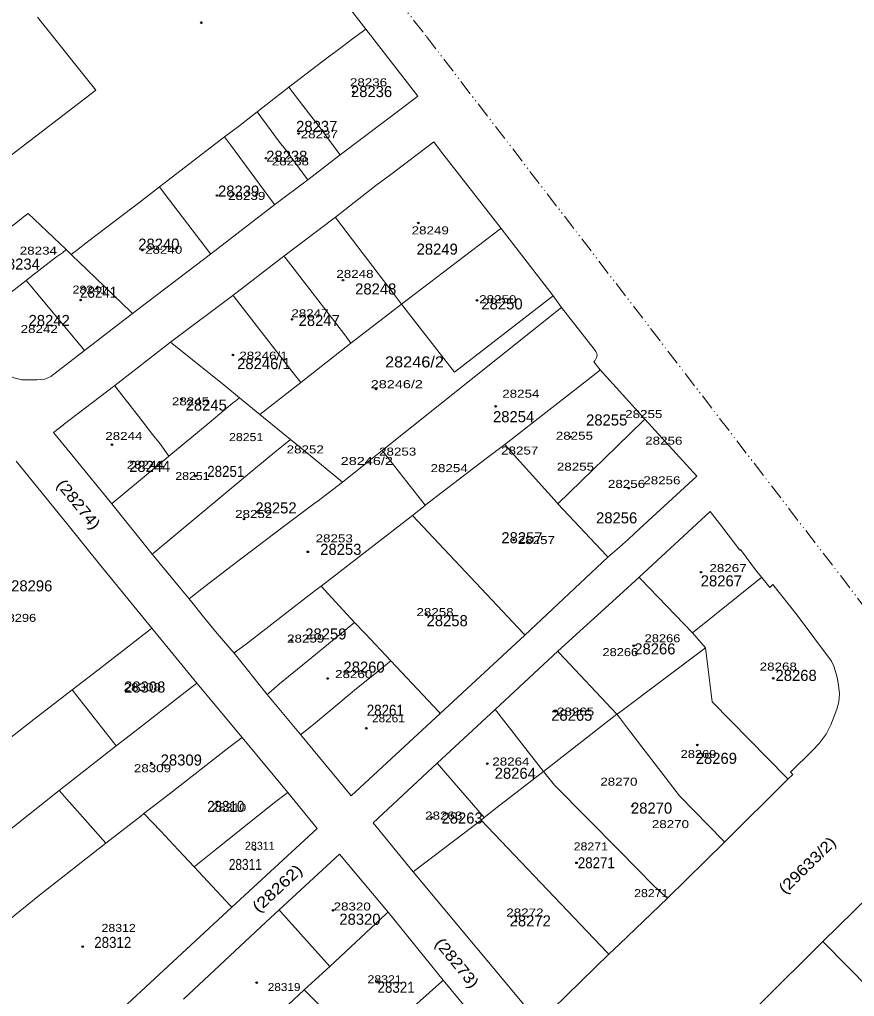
# Model space of a CAD drawing. Extents: x 650553 to 652508, y 239277 to 241647.
# Drawn here: x 651930.1 to 652201.4, y 241075.2 to 241392.6 of the extents above; entities that cross this region are included whole.
import ezdxf

# ---------------------------------------------------------------- set-up
doc = ezdxf.new("R2010")
doc.units = 0
doc.header["$PDMODE"] = 32
doc.header["$PDSIZE"] = 0.5
doc.linetypes.add('DASH_DOUBLE_DOT', pattern=[9.2, 5, -1.2, 0.3, -1.2, 0.3, -1.2])
for name, color, linetype in [('19', 7, 'Continuous'), ('20', 7, 'Continuous'), ('6', 7, 'Continuous')]:
    doc.layers.add(name, color=color, linetype=linetype)
for name, color, linetype, lineweight in [('3', 7, 'Continuous', 13), ('5', 7, 'Continuous', 13), ('52', 7, 'DASH_DOUBLE_DOT', 13)]:
    doc.layers.add(name, color=color, linetype=linetype, lineweight=lineweight)

msp = doc.modelspace()

# ---------------------------------------------------------------- linework, layer by layer
at = {"layer": '3'}
for points in [[(651890.22, 241320.18), (651838.628, 241383.147), (651822.772, 241401.85), (651822.162, 241402.878), (651822.324, 241404.195), (651822.971, 241405.485), (651878.911, 241448.551), (651945.895, 241499.372), (651947.853, 241500.347), (651950.067, 241500.78), (651952.377, 241500.815), (651954.829, 241500.052), (651957.24, 241498.606), (651959.178, 241496.936), (651974.53, 241477.34), (652042.61, 241389.52)], [(652042.61, 241389.52), (652059.5, 241367.66), (652055.39, 241364.52), (652034.26, 241348.65), (652023.73, 241340.54), (652013.04, 241332.49), (651992.17, 241316.41), (651966.8, 241297.11), (651951.21, 241285.1)], [(652032.73, 241328.39), (652045.89, 241338.65), (652050.75, 241342.3), (652064.76, 241352.88)], [(652064.76, 241352.88), (652066.86, 241349.97), (652086.59, 241324.72), (652103.55, 241302.85), (652106.22, 241299.1)], [(651960.07, 241235.27), (651948.05, 241250), (651941.16, 241258.44), (651944.34, 241260.94), (651944.29, 241260.92), (651961.05, 241273.7), (651979.19, 241287.8), (651999.42, 241303), (652016.01, 241315.75), (652032.73, 241328.39)], [(651951.21, 241285.1), (651940.242, 241276.615), (651938.359, 241275.772), (651935.721, 241275.565), (651930.828, 241275.601), (651928.272, 241276.225), (651924.784, 241277.89), (651912.6, 241292.65), (651901.67, 241305.81), (651890.22, 241320.18)], [(652106.22, 241299.1), (652116.84, 241285.49), (652117.34, 241284.77), (652117.73, 241284.14), (652117.75, 241283.42), (652117.6, 241282.82), (652117.38, 241282.34), (652117.06, 241281.74), (652116.74, 241281.45), (652118.8, 241278.81), (652133.285, 241262.755)], [(652133.285, 241262.755), (652150.153, 241244.243), (652131.71, 241227.29), (652127.95, 241223.81), (652125, 241221.2), (652121.3, 241217.93), (652094.34, 241192.6), (652066.77, 241167.17), (652037.87, 241140.4), (652021.41, 241160.31), (652010.56, 241173.28), (651999.81, 241186.77)], [(651929, 241249.08), (651945.44, 241228.9), (651956.13, 241215.68), (651973.06, 241194.89), (651987.72, 241177.05), (652002.397, 241159.358), (652017.226, 241141.527)], [(651985.26, 241204.43), (651982.46, 241207.64), (651973.24, 241218.88), (651960.07, 241235.27)], [(652105.01, 241187.4), (652125, 241205.59), (652131.42, 241211.43), (652154.53, 241232.81)], [(652154.53, 241232.81), (652158.3, 241227.9), (652164.11, 241220.19), (652164.36, 241220.41), (652169.59, 241213.36), (652171.28, 241211.36)], [(652171.28, 241211.36), (652173.87, 241208.14), (652174.89, 241209.06), (652182.74, 241199.12), (652193.93, 241184.19), (652194.75, 241182.55), (652195.76, 241178.96), (652196.2, 241176.3), (652196.52, 241173.55), (652196.32, 241170.97), (652195.66, 241168.53), (652193.75, 241163.5), (652192.17, 241160.44), (652189.93, 241157.46), (652187.72, 241155.1), (652180.61, 241148.14), (652181.34, 241147.34), (652179.79, 241145.85), (652159.18, 241125.35), (652140.6, 241107.17)], [(651999.81, 241186.77), (651994.33, 241193.11), (651990.34, 241197.97), (651985.26, 241204.43)], [(652058.02, 241115.72), (652045.01, 241131.65), (652065.76, 241151.05), (652084.65, 241168.4), (652105.01, 241187.4)], [(652017.226, 241141.527), (652026.85, 241129.84), (651999.05, 241104.25), (651938.56, 241048.11), (651910.25, 241021.92), (651891.181, 241043.471), (651876.36, 241060.41), (651857.991, 241081.221), (651845.55, 241095.34), (651829.37, 241113.9)], [(651983.33, 241074.4), (652010.17, 241099.35), (652014.44, 241103.34), (652034.04, 241121.44)], [(652034.04, 241121.44), (652049.83, 241102.63), (652067.78, 241080.53)], [(652121.57, 241088.99), (652098.88, 241066.75), (652058.02, 241115.72)], [(652140.6, 241107.17), (652125, 241092.27), (652121.57, 241088.99)], [(652150.66, 241053.06), (652170.97, 241073.05), (652191.12, 241093.11), (652206.29, 241107.91)], [(652067.78, 241080.53), (652087.98, 241056.04), (652065.72, 241034.07)]]:
    msp.add_lwpolyline(points, dxfattribs=at)
at = {"layer": '5'}
for p, q in [((651954.88, 241369.62), (651935.96, 241393.37)), ((652035.43, 241384.16), (652038.34, 241386.35)), ((651902.89, 241329.78), (651954.88, 241369.62)), ((651998.65, 241351.86), (651996.74, 241354.45)), ((651932.26, 241307.83), (651934.14, 241305.63)), ((652037.75, 241287.47), (652035.78, 241290.15)), ((652021.49, 241274.69), (652019.39, 241277.35)), ((652018.16, 241256.2), (652013.07, 241252.05)), ((652087.74, 241254.55), (652081.78, 241250)), ((652013.07, 241252.05), (652010.57, 241250)), ((652047.94, 241252.56), (652044.71, 241250)), ((652047.94, 241252.56), (652049.95, 241250)), ((651977.78, 241250), (651963.65, 241238.32)), ((651978.66, 241250.72), (651977.78, 241250)), ((652010.57, 241250), (652006.18, 241246.4)), ((652025.7, 241250), (652035.03, 241242.33)), ((652044.71, 241250), (652035.03, 241242.33)), ((652081.78, 241250), (652061.877, 241234.823)), ((652091.81, 241250), (652104.77, 241235.55)), ((652120.15, 241250), (652105.012, 241235.292)), ((652035.03, 241242.33), (652026.74, 241235.96)), ((652104.77, 241235.55), (652105.012, 241235.292)), ((652061.95, 241234.73), (652057.83, 241231.51)), ((652152.95, 241188.53), (652148.8, 241193.31)), ((652152.95, 241188.53), (652125, 241167.51)), ((651947.2, 241174.85), (651961.55, 241156.66)), ((652124.17, 241166.89), (652125, 241167.51)), ((652127.62, 241162.41), (652125, 241165.81)), ((652065.76, 241151.05), (652081.05, 241133.37)), ((651943.01, 241142.12), (651958.13, 241124.99))]:
    msp.add_line(p, q, dxfattribs=at)
for points in [[(652038.34, 241386.35), (652038.34, 241386.28), (652042.61, 241389.52)], [(652017.58, 241370.58), (652028.69, 241379.04), (652035.43, 241384.16)], [(652007.34, 241362.6), (652017.58, 241370.58), (652021.35, 241365.68), (652025.49, 241360.31), (652026.44, 241359.17)], [(651996.74, 241354.45), (652001.23, 241357.84), (652007.34, 241362.6), (652014.92, 241352.3), (652016.16, 241350.78)], [(652026.44, 241359.17), (652033.888, 241349.15), (652034.26, 241348.65)], [(651975.54, 241338.21), (651978.4, 241340.43), (651993.5, 241351.96), (651996.74, 241354.45)], [(651998.65, 241351.86), (652012.669, 241332.99), (652013.04, 241332.49)], [(652016.16, 241350.78), (652023.36, 241341.04), (652023.73, 241340.54)], [(651946.89, 241316.31), (651948.6, 241317.55), (651952.22, 241320.34), (651969.75, 241333.72), (651975.54, 241338.21), (651977.42, 241335.72)], [(651977.42, 241335.72), (651991.788, 241316.91), (651992.17, 241316.41)], [(651901.67, 241305.81), (651902.17, 241306.192), (651914.22, 241315.39), (651917.79, 241318.11), (651928.9, 241326.49), (651931.27, 241328.35)], [(651931.27, 241328.35), (651932.92, 241329.62), (651945.26, 241317.85)], [(652051.86, 241303.3), (652033.111, 241327.89), (652032.73, 241328.39)], [(652086.59, 241324.72), (652086.09, 241324.341), (652054.18, 241300.13)], [(651912.6, 241292.65), (651913.1, 241293.036), (651932.26, 241307.83), (651933.94, 241309.27), (651942.09, 241315.47), (651944.08, 241316.85), (651945.26, 241317.85)], [(651945.26, 241317.85), (651946.89, 241316.31), (651947.46, 241315.77), (651949.27, 241313.99)], [(652035.78, 241290.15), (652016.396, 241315.25), (652016.01, 241315.75)], [(651949.27, 241313.99), (651966.3, 241297.591), (651966.8, 241297.11)], [(651934.14, 241305.63), (651950.794, 241285.6), (651951.21, 241285.1)], [(652019.39, 241277.35), (651999.809, 241302.5), (651999.42, 241303)], [(652054.18, 241300.13), (652052.27, 241302.78), (652051.86, 241303.3)], [(652054.18, 241300.13), (652071.44, 241278.03), (652103.05, 241302.464), (652103.55, 241302.85)], [(652054.18, 241300.13), (652037.75, 241287.47), (652021.49, 241274.69), (652008.13, 241264.27)], [(652047.94, 241252.56), (652105.72, 241298.701), (652106.22, 241299.1)], [(651997.08, 241273.36), (651979.69, 241287.396), (651979.19, 241287.8)], [(652118.8, 241278.81), (652118.3, 241278.419), (652087.74, 241254.55), (652091.81, 241250)], [(651961.05, 241273.7), (651961.437, 241273.2), (651968.78, 241263.72), (651973.25, 241257.76), (651975.75, 241254.77), (651978.66, 241250.72), (651991.05, 241260.99), (651999.28, 241267.92), (651999.94, 241268.42), (652001.55, 241269.71)], [(652008.13, 241264.27), (652001.55, 241269.71), (651997.08, 241273.36)], [(652008.13, 241264.27), (652018.16, 241256.2), (652025.7, 241250)], [(652133.285, 241262.755), (652132.785, 241262.269), (652120.15, 241250)], [(652049.95, 241250), (652061.877, 241234.823), (652061.95, 241234.73)], [(652006.18, 241246.4), (651973.74, 241219.298), (651973.24, 241218.88)], [(651963.65, 241238.32), (651960.57, 241235.696), (651960.07, 241235.27)], [(652026.74, 241235.96), (652026.14, 241235.58), (652017.04, 241228.77)], [(652105.012, 241235.292), (652120.831, 241218.43), (652121.3, 241217.93)], [(652017.04, 241228.77), (651998.76, 241214.95), (651989.33, 241207.61)], [(652057.83, 241231.51), (652028.13, 241208.49), (652031.56, 241204.71), (652038.97, 241196.72), (652023.91, 241184.36), (652014.59, 241176.76)], [(652057.83, 241231.51), (652093.871, 241193.1), (652094.34, 241192.6)], [(652148.8, 241193.31), (652131.9, 241210.93), (652131.42, 241211.43)], [(652148.8, 241193.31), (652170.78, 241210.959), (652171.28, 241211.36)], [(651989.33, 241207.61), (651985.76, 241204.821), (651985.26, 241204.43)], [(652028.13, 241208.49), (652026.11, 241207.06), (652003.83, 241189.82)], [(651973.06, 241194.89), (651972.56, 241194.495), (651969.58, 241192.14), (651955.5, 241181.26), (651947.2, 241174.85), (651933.89, 241164.53), (651924.37, 241157.06)], [(652038.97, 241196.72), (652042.45, 241193.17), (652050.77, 241184.27)], [(652003.83, 241189.82), (652000.31, 241187.149), (651999.81, 241186.77)], [(652179.79, 241145.85), (652179.3, 241146.35), (652155.14, 241170.98), (652152.95, 241188.53)], [(652105.01, 241187.4), (652105.477, 241186.9), (652124.17, 241166.89)], [(652050.77, 241184.27), (652044.95, 241179.5), (652039.58, 241175.25), (652037.54, 241173.52), (652025.62, 241163.62)], [(652050.77, 241184.27), (652066.302, 241167.67), (652066.77, 241167.17)], [(651987.72, 241177.05), (651983.87, 241174.06), (651967.51, 241161.35), (651961.55, 241156.66), (651943.01, 241142.12)], [(652014.59, 241176.76), (652011.06, 241173.712), (652010.56, 241173.28)], [(652084.65, 241168.4), (652085.04, 241167.9), (652100.33, 241148.31)], [(652125, 241165.81), (652124.17, 241166.89), (652100.33, 241148.31)], [(652025.62, 241163.62), (652021.91, 241160.703), (652021.41, 241160.31)], [(652159.18, 241125.35), (652158.693, 241125.85), (652144.55, 241140.37), (652127.62, 241162.41)], [(652002.397, 241159.358), (651998.13, 241156.13), (651978.67, 241140.99), (651970.49, 241134.72), (651969.5, 241133.8), (651958.13, 241124.99), (651936.57, 241108.11)], [(652121.57, 241088.99), (652121.094, 241089.49), (652080.08, 241132.53), (652081.05, 241133.37), (652085.16, 241136.58), (652100.33, 241148.31), (652103.95, 241143.85), (652125, 241122.54)], [(651943.01, 241142.12), (651893.01, 241102.49), (651889.49, 241100.9), (651879.41, 241099.07), (651857.991, 241081.221)], [(652017.226, 241141.527), (652012.93, 241138.21), (651993.83, 241122.96), (651986.85, 241117.39)], [(651970.49, 241134.72), (651976.01, 241128.9), (651981.59, 241122.85), (651986.85, 241117.39)], [(652080.08, 241132.53), (652058.52, 241116.101), (652058.02, 241115.72)], [(652140.6, 241107.17), (652140.1, 241107.629), (652136.2, 241111.21), (652125, 241122.54)], [(651986.85, 241117.39), (651998.586, 241104.75), (651999.05, 241104.25)], [(651936.57, 241108.11), (651920.48, 241095.11), (651919.7, 241094.44), (651916.06, 241091.42)], [(652014.44, 241103.34), (652014.889, 241102.84), (652030.93, 241084.96)], [(652030.93, 241084.96), (652049.33, 241102.163), (652049.83, 241102.63)], [(652191.12, 241093.11), (652191.613, 241092.61), (652221.38, 241062.42), (652200.98, 241042.45)], [(652030.93, 241084.96), (652022.59, 241077.39), (651999.92, 241056.14)], [(652067.78, 241080.53), (652067.28, 241080.083), (652042.2, 241057.65), (652022.59, 241077.39)]]:
    msp.add_lwpolyline(points, dxfattribs=at)
at = {"layer": '52'}
msp.add_lwpolyline([(651848.117, 241638.653), (651850.85, 241640.826), (651854.855, 241643.843), (651859.061, 241646.967), (651862.077, 241642.993), (651865.187, 241639.299), (651868.69, 241635.11), (651876.454, 241625.813), (651886.134, 241613.883), (651968.083, 241508.86), (652062.325, 241387.051), (652163.19, 241255.731), (652270.107, 241116.584), (652399.768, 240948.012), (652508.14, 240805.294)], dxfattribs=at)
at = {"layer": '6'}
for p in [(651989.203, 241391.575), (652038.565, 241369.085), (652020.822, 241355.56), (652010.204, 241347.545), (651994.249, 241335.43), (652059.681, 241326.505), (651969.979, 241317.66), (652035.189, 241307.93), (651949.931, 241301.475), (652078.731, 241301.375), (652018.671, 241295.22), (651999.423, 241283.635), (652045.91, 241272.59), (651982.739, 241269.26), (652084.802, 241266.961), (651960.172, 241254.485), (652109.177, 241257.051), (651987.269, 241244.295), (652128.059, 241240.342), (652003.016, 241230.315), (652090.64, 241223.575), (652023.772, 241219.665), (652151.513, 241213.06), (652062.278, 241199.34), (652018.533, 241190.885), (652129.674, 241189.16), (652030.224, 241178.515), (652175.004, 241178.605), (651967.238, 241175.775), (652104.172, 241167.855), (652042.768, 241162.335), (652150.367, 241156.94), (651972.96, 241151.02), (652082.111, 241150.885), (651994.2, 241138.374), (652129.245, 241137.03), (652063.951, 241133.385), (652006.519, 241122.888), (652111.076, 241118.65), (652031.959, 241103.2), (652091.429, 241099.64), (651950.642, 241091.415), (652007.127, 241079.74), (652046.482, 241080.14)]:
    msp.add_point(p, dxfattribs=at)

# ---------------------------------------------------------------- texts
at = {"layer": '19'}
for s, p in [('28236', (652037.793, 241367.396)), ('28237', (652019.975, 241356.081)), ('28238', (652010.254, 241346.382)), ('28239', (651994.596, 241335.067)), ('28240', (651968.677, 241317.824)), ('28249', (652059.123, 241316.207)), ('28234', (651923.319, 241311.358)), ('28248', (652039.144, 241303.275)), ('28250', (652080.181, 241298.425)), ('28242', (651933.039, 241293.038)), ('28247', (652020.786, 241293.037)), ('28246/1', (652000.805, 241279.026)), ('28245', (651984.067, 241265.557)), ('28254', (652083.958, 241261.785)), ('28255', (652114.196, 241260.707)), ('28244', (651965.708, 241245.62)), ('28252', (652006.744, 241232.15)), ('28256', (652117.437, 241228.917)), ('28257', (652086.659, 241222.451)), ('28253', (652027.802, 241218.679)), ('28296', (651927.37, 241206.825)), ('28267', (652151.455, 241208.442)), ('28258', (652062.36, 241195.51)), ('28259', (652022.944, 241191.199)), ('28266', (652129.857, 241186.35)), ('28260', (652035.362, 241180.423)), ('28268', (652175.754, 241177.729)), ('28308', (651964.087, 241173.957)), ('28265', (652102.858, 241164.797)), ('28309', (651975.967, 241150.249)), ('28269', (652149.836, 241150.788)), ('28264', (652084.499, 241145.938)), ('28270', (652128.777, 241134.623)), ('28263', (652067.221, 241131.39)), ('28320', (652034.012, 241098.519)), ('28272', (652089.361, 241097.983))]:
    msp.add_text(s, height=3.6, dxfattribs=at).set_placement(p)
for s, width, p in [('28241', 0.9, (651949.778, 241302.198)), ('28246/2', 1.1, (652048.861, 241279.565)), ('28251', 0.9, (651991.085, 241244.004)), ('28261', 0.9, (652042.922, 241166.413)), ('28310', 0.9, (651991.085, 241135.161)), ('28311', 0.8, (651998.105, 241116.303)), ('28271', 0.9, (652111.499, 241116.842)), ('28312', 0.9, (651954.368, 241090.978)), ('28321', 0.9, (652046.432, 241076.428))]:
    msp.add_text(s, height=3.6, dxfattribs=dict(at, width=width)).set_placement(p)
for s, rotation, width, p in [('(28274)', 308.96, 1.15, (651941.896, 241241.414)), ('(29633/2)', 44.545, 1.15, (652178.87, 241108.274)), ('(28262)', 42.91, 1.2, (652007.781, 241102.269)), ('(28273)', 309.084, 1.15, (652064.851, 241092.397))]:
    msp.add_text(s, height=3.6, rotation=rotation, dxfattribs=dict(at, width=width)).set_placement(p)
at = {"layer": '20'}
for s, width, p in [('28236', 1.25, (652037.459, 241370.916)), ('28237', 1.25, (652021.457, 241354.021)), ('28238', 1.25, (652012.071, 241345.208)), ('28239', 1.25, (651997.873, 241334)), ('28249', 1.25, (652057.51, 241322.806)), ('28234', 1.25, (651930.166, 241316.216)), ('28240', 1.25, (651970.889, 241316.517)), ('28248', 1.25, (652033.043, 241308.663)), ('28241', 1.15, (651947.329, 241303.573)), ('28250', 1.25, (652079.462, 241300.444)), ('28247', 1.25, (652018.43, 241295.874)), ('28242', 1.25, (651930.449, 241290.763)), ('28246/1', 1.25, (652001.513, 241282.107)), ('28246/2', 1.35, (652044.213, 241272.835)), ('28254', 1.25, (652086.939, 241269.739)), ('28245', 1.25, (651979.606, 241267.26)), ('28255', 1.25, (652126.901, 241263.126)), ('28244', 1.25, (651957.955, 241256.015)), ('28251', 1.15, (651998.179, 241255.643)), ('28255', 1.25, (652104.358, 241256.086)), ('28252', 1.25, (652016.894, 241251.648)), ('28256', 1.25, (652133.408, 241254.483)), ('28253', 1.25, (652046.926, 241250.936)), ('28257', 1.25, (652086.584, 241251.287)), ('28244', 1.25, (651964.96, 241246.661)), ('28246/2', 1.35, (652034.457, 241247.889)), ('28254', 1.25, (652063.657, 241245.559)), ('28255', 1.25, (652104.697, 241246.038)), ('28251', 1.15, (651980.719, 241243.009)), ('28256', 1.25, (652121.295, 241240.444)), ('28256', 1.25, (652132.786, 241241.615)), ('28252', 1.25, (652000.158, 241230.663)), ('28253', 1.25, (652026.31, 241222.752)), ('28257', 1.25, (652092.006, 241222.186)), ('28267', 1.25, (652154.281, 241213.088)), ('28258', 1.25, (652059.076, 241198.787)), ('28296', 1.2, (651923.906, 241196.917)), ('28259', 1.25, (652017.038, 241190.197)), ('28266', 1.2, (652133.224, 241190.291)), ('28266', 1.2, (652119.51, 241185.801)), ('28260', 1.25, (652032.633, 241178.662)), ('28268', 1.25, (652170.607, 241181.104)), ('28308', 1.25, (651963.937, 241174.381)), ('28265', 1.25, (652104.74, 241166.478)), ('28261', 1.1, (652044.645, 241164.291)), ('28264', 1.25, (652083.716, 241150.251)), ('28269', 1.2, (652144.92, 241152.694)), ('28309', 1.25, (651967.248, 241148.075)), ('28270', 1.25, (652118.808, 241143.704)), ('28310', 1.15, (651992.605, 241135.342)), ('28263', 1.25, (652061.897, 241132.704)), ('28270', 1.25, (652135.562, 241129.916)), ('28271', 1.15, (652110.179, 241122.674)), ('28271', 1.15, (652129.811, 241107.498)), ('28320', 1.25, (652032.145, 241103.16)), ('28272', 1.25, (652088.272, 241101.204)), ('28312', 1.15, (651956.744, 241096.194)), ('28319', 1.1, (652010.757, 241076.992)), ('28321', 1.15, (652043.171, 241079.517))]:
    msp.add_text(s, height=2.6, dxfattribs=dict(at, width=width)).set_placement(p)
msp.add_text('28311', height=2.6, dxfattribs=at).set_placement((652003.336, 241122.897))

doc.saveas('drawing.dxf')
